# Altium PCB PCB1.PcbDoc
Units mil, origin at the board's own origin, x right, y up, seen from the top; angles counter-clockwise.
Board outline 6000 x 4000 mil, 2 copper layers (Top Layer, Bottom Layer); 39 components, 37 nets, 123 pads, 0 vias.
Unrouted connection lines stored in the file: 1.
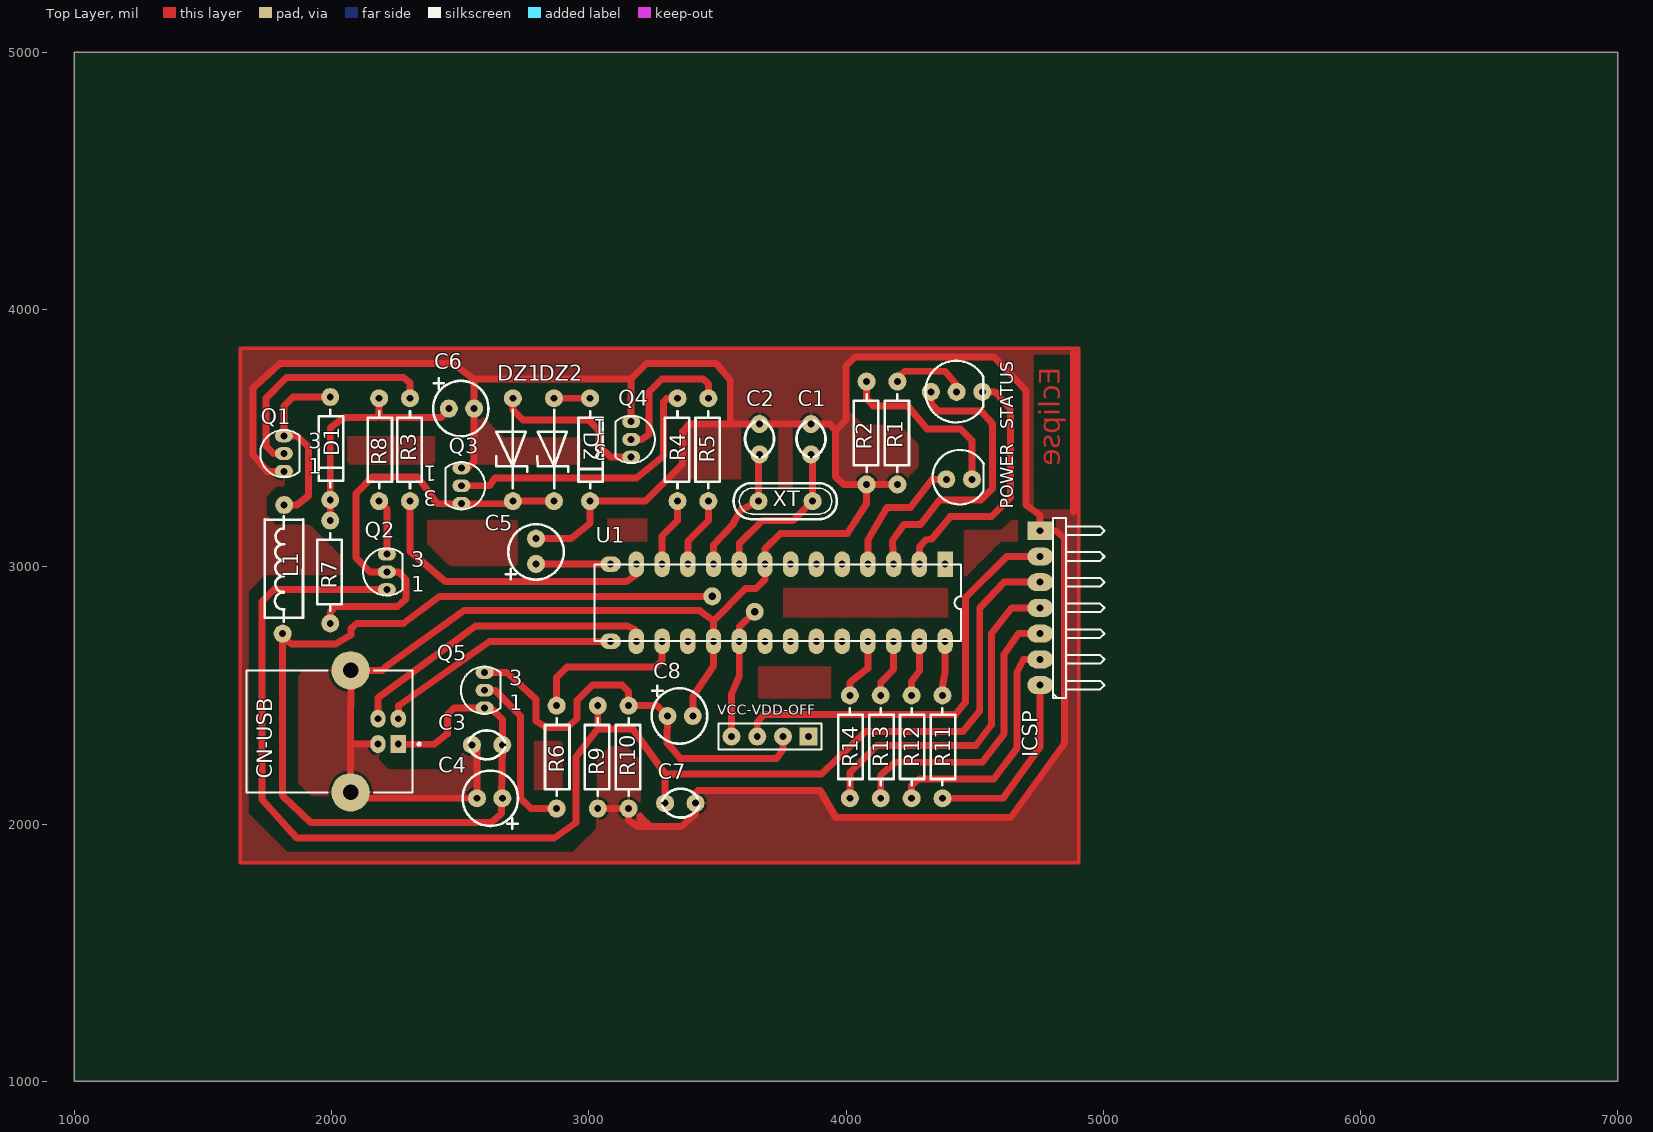
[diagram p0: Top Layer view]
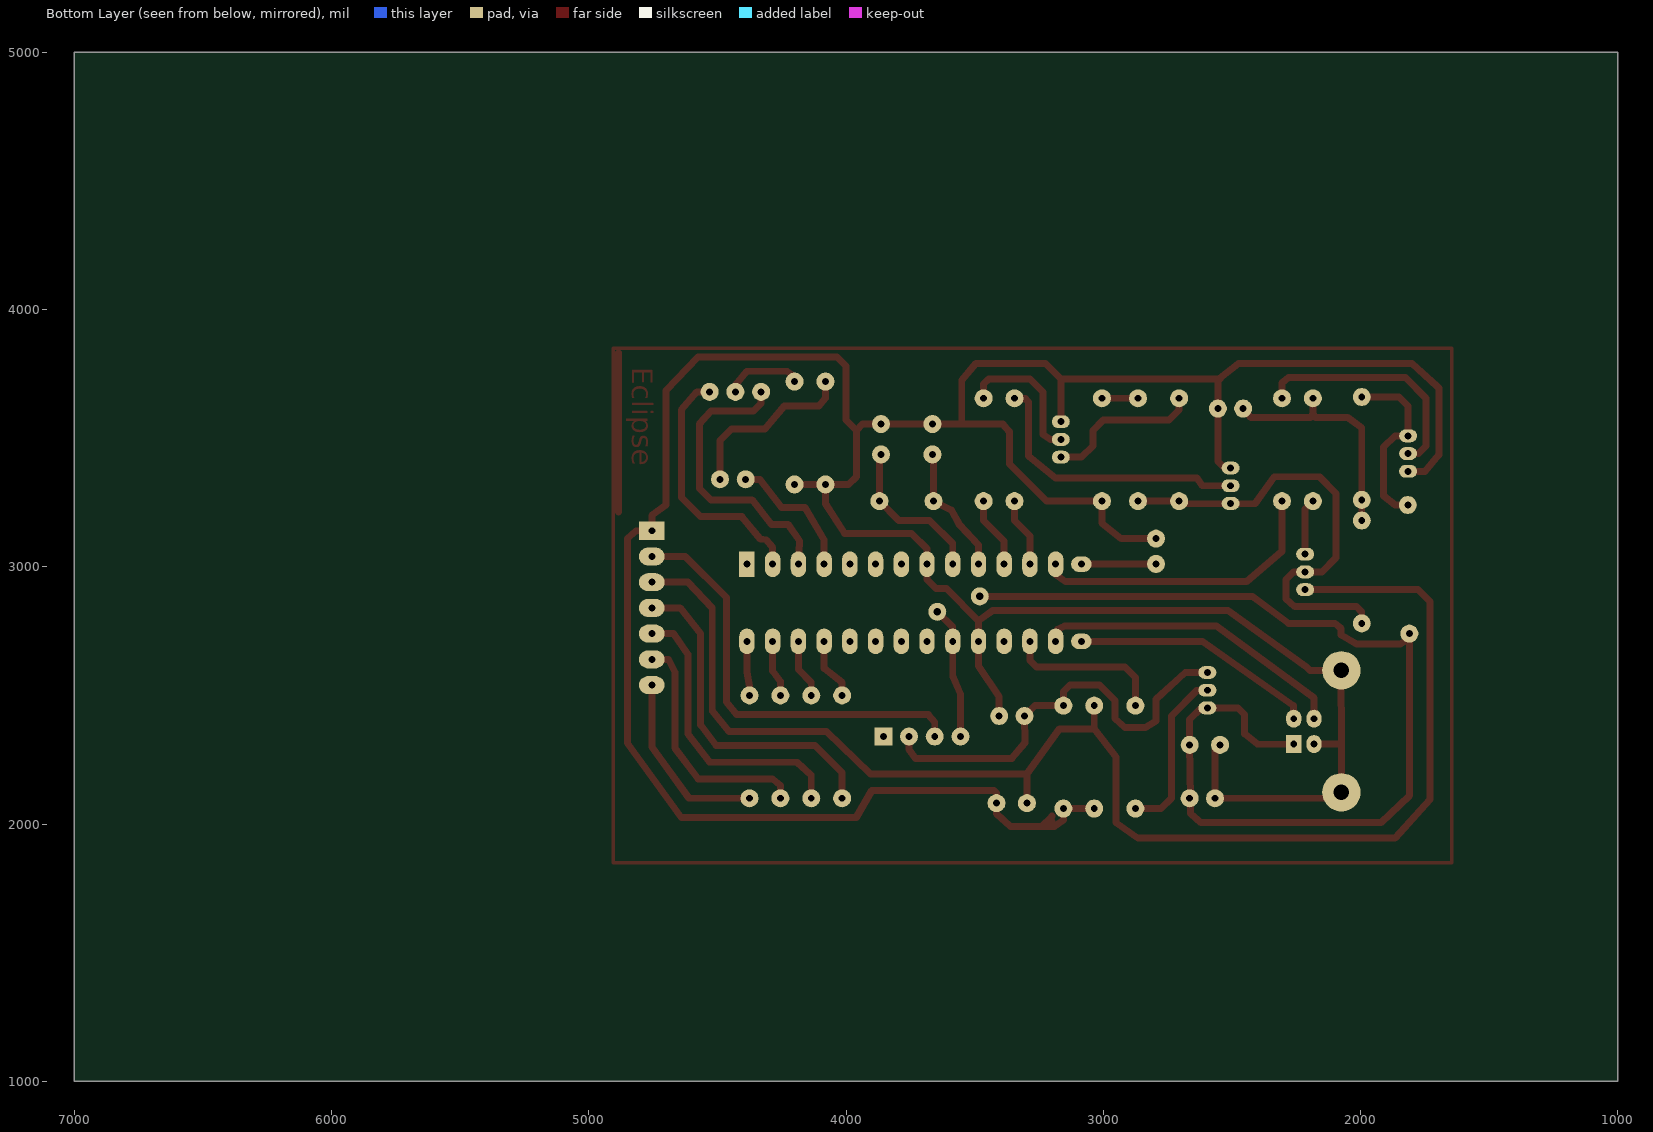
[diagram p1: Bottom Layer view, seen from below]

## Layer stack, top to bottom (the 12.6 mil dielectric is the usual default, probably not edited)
Top Layer: signal copper 1.4
Dielectric: dielectric 12.6, FR-4, Dk 4.8
Bottom Layer: signal copper 1.4

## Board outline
1000,1000 7000,1000 7000,5000 1000,5000

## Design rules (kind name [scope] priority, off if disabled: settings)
Clearance [All] p1: gap=10
ComponentClearance [All] p1: gap=10 collisioncheckmode=0
PolygonConnect [All] p1: connectstyle=Relief reliefconductorwidth=10 reliefentries=4 polygonreliefangle="90 Angle"
RoomDefinition "" [InComponentClass('Sheet1')] p1: confinementstyle=ConfineIn formatcopy=TRUE outline 1645,1850 4905,1850 4905,3850 1645,3850
RoutingLayers [All] p1: top layer=Horizontal bottom layer=Vertical
RoutingVias [All] p1: holewidth=28 width=50 viastyle="Through Hole" minholewidth=28 minwidth=50 maxholewidth=28 maxwidth=50
SolderMaskExpansion [All] p1: expansion=4
TestPointUsage [All] p1: valid=0 allowmultiple=FALSE
Testpoint [All] p1: side=15 testpointundercomponent=TRUE minsize=40 maxsize=100 preferedsize=60 minholesize=0 maxholesize=40 preferedholesize=32 testpointgrid=1 style=1023 order=-539222988
Width [All] p1: maxlimit=27 minlimit=27 preferedwidth=27
16 further rules are at their usual default settings.

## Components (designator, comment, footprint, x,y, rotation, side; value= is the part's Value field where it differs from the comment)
C1 "CC" "CC 0.15" 3865,3495 r270 top
C2 "CC" "CC 0.15" 3665,3495 r270 top
C3 "CC" "CC 0.15" 2605.57,2308.65 r0 top
C4 "Cap" CE-1.7 2615,2100 r180 top
C5 "Cap" CE-1.7 2795,3060 r90 top
C6 "Cap" CE-1.7 2505,3615 r0 top
C7 "CC" "CC 0.15" 3355,2080 r180 top
C8 "Cap" CE-1.7 3355,2420 r0 top
CN-USB "USB V2.0" USB2.5-2H4D 2220,2360 r180 top
D1 "Diodo" "DIODO 4MIL" 1995,3460 r270 top
D2 "Diodo" "DIODO 4MIL" 3005,3455 r270 top
DZ1 "5.6V" DIODOZ 2705,3455 r270 top
DZ2 "13V" DIODOZ 2865,3455 r270 top
ICSP "ICSP" HDR1X7H 4755,2540 r90 top (schematic designator JP1)
L1 "Inductor" L 1815,3040 r90 top
POWER "LED" LED-0 4440,3340 r0 top
Q1 "2N3904" "Q123 0.1" 1815,3440 r0 top
Q2 "2N3904" "Q123 0.1" 2215,2980 r0 top
Q3 "2N3904" "Q123 0.1" 2505,3315 r180 top
Q4 "2N3904" "Q123 0.1" 3165,3495 r180 top
Q5 "2N3906" "Q123 0.1" 2595,2520 r0 top
R1 "Res" "AXIAL 4MIL" 4200,3520 r90 top
R2 "Res" "AXIAL 4MIL" 4080,3520 r90 top
R3 "Res" "AXIAL 4MIL" 2305,3455 r90 top
R4 "Res" "AXIAL 4MIL" 3345,3455 r90 top
R5 "Res" "AXIAL 4MIL" 3465,3455 r90 top
R6 "Res" "AXIAL 4MIL" 2875,2260 r270 top
R7 "Res" "AXIAL 4MIL" 1995,2980 r90 top
R8 "Res" "AXIAL 4MIL" 2185,3455 r270 top
R9 "Res" "AXIAL 4MIL" 3035,2260 r90 top
R10 "Res" "AXIAL 4MIL" 3155,2260 r90 top
R11 "Res" "AXIAL 4MIL" 4375,2300 r270 top
R12 "Res" "AXIAL 4MIL" 4255,2300 r270 top
R13 "Res" "AXIAL 4MIL" 4135,2300 r270 top
R14 "Res" "AXIAL 4MIL" 4015,2300 r270 top
STATUS "LED" LED-BI 4380,3680 r0 top
U1 "PIC18F2550" DIP-28 3735,2860 r180 top
VCC-VDD-OFF "INPUT" HDR1X4 3855,2340 r180 top (schematic designator "CTRL 1")
XT "20MHz" "XT 0.17" 3765,3255 r0 top

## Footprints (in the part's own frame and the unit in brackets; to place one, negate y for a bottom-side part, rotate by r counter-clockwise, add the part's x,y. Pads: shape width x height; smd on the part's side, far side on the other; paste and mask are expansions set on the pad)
"AXIAL 4MIL" [mil]
  round 70 hole 27: 1(-200,0) 2(200,0)
  silkscreen extent -150,-45 150,50
"CC 0.15" [mil]
  round 70 hole 27: 1(-59.78,-1) 2(58.33,-1)
  silkscreen extent -74,-57 69,55
CE-1.7 [mil]
  round 70 hole 27: 1(-49,0) 2(49.43,0)
  silkscreen extent -110,-108 105,118
"DIODO 4MIL" [mil]
  round 70 hole 27: 1(-200,0) 2(200,0)
  silkscreen extent -150,-45 150,50
DIODOZ [mil]
  round 70 hole 27: 1(-200,0) 2(200,0)
  silkscreen extent -155,-65 150,56
DIP-28 [mil]
  rect 60x100 hole 27: 1(-650,-150)
  oval 60x100 hole 27: 2(-550,-150) 3(-450,-150) 4(-350,-150) 5(-250,-150) 6(-150,-150) 7(-50,-150) 8(50,-150) 9(150,-150) 10(250,-150) 11(350,-150) 12(450,-150) 13(550,-150) 16(550,150) 17(450,150) 18(350,150) 19(250,150) 20(150,150) 21(50,150) 22(-50,150) 23(-150,150) 24(-250,150) 25(-350,150) 26(-450,150) 27(-550,150) 28(-650,150)
  oval 80x60 hole 27: 14(650,-150) 15(650,150)
  silkscreen extent -713,-149 713,149
HDR1X4 [mil]
  rect 70x70 hole 27: 1(0,0)
  round 70 hole 27: 2(100,0) 3(200,0) 4(300,0)
  silkscreen extent -50,-50 350,50
HDR1X7H [mil]
  rect 70x100 hole 27: 1(600,0)
  oval 70x100 hole 27: 2(500,0) 3(400,0) 4(300,0) 5(200,0) 6(100,0) 7(0,0)
  silkscreen extent -50,-250 650,-50
L [mil]
  round 70 hole 27: 1(-300,5) 2(200,-1)
  silkscreen extent -253,-75 156,75
LED-0 [mil]
  round 70 hole 27: 1(-50,0) 2(50,0)
  silkscreen extent -103,-98 95,114
LED-BI [mil]
  round 70 hole 27: 1(-50,0) 2(150,0) 3(50,0)
  silkscreen extent -71,-119 153,121
"Q123 0.1" [mil]
  oval 70x50 hole 27: 1(0,-68.9) 2(0,0) 3(0,68.9)
  silkscreen extent -92,-92 61,92
USB2.5-2H4D [mil]
  rect 60x70 hole 27: 1(-39.37,49.21)
  oval 60x70 hole 27: 2(-39.37,-49.21) 3(39.37,-49.21) 4(39.37,49.21)
  round 149.61 hole 60: 5(146.06,237.01) 6(146.06,-237.01)
  silkscreen extent -125,-237 551,237
"XT 0.17" [mil]
  round 70 hole 27: 1(-105,0) 2(105,0)
  silkscreen extent -202,-70 200,70

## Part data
C1 C2 C3 C7: library part "Cap C", "Capacitor Ceramico"
C4 C5 C6 C8: library part "Cap E", "Capacitor Electrolitico"
CN-USB: library part "CON USB", "CON USB"
D1 D2: "Diodo de uso general"
DZ1 DZ2: library part "D Zener", "Diodo Zener"
ICSP: library part "Header 7", "Header, 7-Pin"
Q1 Q2 Q3 Q4: "NPN Uso general"
Q5: "PNP Uso General"
R1 R2 R3 R4 R5 R6 R7 R8 R9 R10 R11 R12 R13 R14: "Resistor"
STATUS: library part LED_BI, "LED_BI"
U1: "High Performance, Microcontroller with 10-Bit A/D, 16K EPROM, 28-Pin SOIC, Standard Volt Range, Extended Temperature"
VCC-VDD-OFF: library part "CON VDD/VCC", "CON VDD/VCC"
XT: library part XTAL, "Crystal Oscillator"

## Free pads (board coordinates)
  round 70 hole 30: 0(3480,2885) 1(3645,2825)

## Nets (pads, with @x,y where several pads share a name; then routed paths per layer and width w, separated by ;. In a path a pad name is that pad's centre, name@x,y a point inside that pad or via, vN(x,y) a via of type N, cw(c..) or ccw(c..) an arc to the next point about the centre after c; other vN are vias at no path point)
GND: C1.1 C2.1 C3.1 C4.2 C5.2 C6.2 C7.1 C8.2 CN-USB.4 CN-USB.5 CN-USB.6 D2.2 ICSP.1 Q1.1 Q3.1 Q4.1 R1.1 R2.1 R9.1 R10.1 U1.8 U1.19 | length 14553.9
  Top Layer w27: Q1.1 1750,3370 1695,3435 1695,3695 1703.01,3702.25 1800,3790 2475,3790 2546.57,3731.94 2548.97,3730 2554.43,3725.57 2554.43,3409.43 2528.9,3383.9 Q3.1 ; CN-USB.5@2070,2100 C4.2 2565.57,2287.86 C3.1 ; CN-USB.5 2074.37,2315 2075,2595.95 CN-USB.6 2197.01,2597.01 2210,2610 2515,2830 3430,2830 3485,2790 ; 2075,2315 2079.21,2310.79 CN-USB.4 ; 2545,3730 3165,3730 ; C5.2 2929.43,3109.43 3005,3170 D2.2 3220,3255 3365,3400 3365,3525 3390,3555 3550,3554.84 3664,3554.89 C1.1@3864,3554.98 ; R9.1 R10.1 ; R10.1@3160,2055 R10.1 ; Q4.1 3165,3730 ; 3200,2010 3220,1990 ; 3200,2032 3200,2030 3240,1990 ; C8.2 3405,2495 3485,2615 3485,2790 ; C7.1 C7.1@3419,2081 ; 3550,3555 3550,3725 3495,3790 3225,3790 3165,3730 ; C1.1 3935.22,3554.78 3960,3530 ; R2.1 4080,3245 4005,3130 3745,3130 3685,3070 3685,2950 3650,2915 3610,2915 3485,2790 ; R1.1 3990,3320 3960,3350 3960,3530 ; 4885,3213 4885,3832 ; R10.1 3155,2015 3187.16,1992.03 3190,1990 3360,1990 3414.78,2039.78 3414.78,2119.78 3425,2130 3900,2130 3960,2025 4640,2025 4850,2315 4850,3110 4815,3140 ICSP.1 4755,3200 4700,3240 4700,3685 4575,3815 4035,3815 4000,3780 4000,3570 3960,3530
NetC1_2: C1.2 U1.9 XT.2 | length 617.5
  Top Layer w27: U1.9 3585,3090 3675,3180 3795,3180 XT.2 3870,3430.67 C1.2
NetC2_2: C2.2 U1.10 XT.1 | length 508.9
  Top Layer w27: U1.10 3485,3085 3560,3165 3590,3220 XT.1 3660,3432.67 C2.2
NetC5_1: C5.1 U1.14 | length 290.4
  Top Layer w27: C5.1 3084,3011 U1.14
NetC6_1: C6.1 D1.2 R7.2 R8.1 | length 926.2
  Top Layer w27: R7.2 1995,3540 2050,3580 2175,3580 2185,3595 ; R8.1 2185,3595 ; C6.1 2426,3580 2195,3580 2185,3595
NetCN-USB_2: CN-USB.2 U1.15 | length 960
  Top Layer w27: CN-USB.2@2259.37,2404.21 2260,2460 2615,2710 U1.15
NetCN-USB_3: CN-USB.3 U1.16 | length 1221.6
  Top Layer w27: CN-USB.3 2180,2490 2560,2770 3150,2770 3180,2755 U1.16
NetD1_1: D1.1 L1.2 Q1.3 | length 719.8
  Top Layer w27: L1.2 1865,3240 1910,3275 1910,3465 1866.1,3508.9 Q1.3 1815,3625 1850,3660 D1.1
NetD2_1: D2.1 DZ2.1 | length 140
  Top Layer w27: DZ2.1 D2.1
NetDZ1_1: DZ1.1 Q4.3 | length 616.3
  Top Layer w27: DZ1.1 2705,3610 2745,3570 3000,3570 3040,3530 3040,3470 3083.9,3426.1 Q4.3
NetDZ1_2: DZ1.2 DZ2.2 Q2.2 Q3.3 R7.1 | length 1767.2
  Top Layer w27: R7.1 1995,2825 2015,2845 2255,2845 2290,2875 2290,2950 2260,2980 2150,2980 2095,3035 2095,3285 2160,3350 2335,3350 2410,3245 Q3.3 2675,3245 DZ1.2 DZ2.2
NetJP1_4: ICSP.4 R14.2 | length 1331.6
  Top Layer w27: R14.2@4015,2095 4015,2200 4120,2305 4505,2305 4565,2385 4565,2740 4645,2840 ICSP.4
NetJP1_5: ICSP.5 R13.2 | length 1135.4
  Top Layer w27: R13.2 4135,2190 4190,2240 4530,2240 4615,2350 4615,2660 4670,2740 ICSP.5
NetJP1_6: ICSP.6 R12.2 | length 945
  Top Layer w27: R12.2 4255,2150 4285,2175 4575,2175 4665,2295 4665,2590 4690,2640 ICSP.6
NetJP1_7: ICSP.7 R11.2 | length 722
  Top Layer w27: R11.2 4610,2100 4755,2300 ICSP.7
NetPOWER_1: POWER.1 U1.4 | length 524.8
  Top Layer w27: U1.4 4085,3105 4160,3230 4250,3230 4335,3340 POWER.1
NetPOWER_2: POWER.2 R2.2 | length 699.8
  Top Layer w27: R2.2 4080,3655 4105,3625 4240,3625 4315,3535 4445,3535 4490,3490 POWER.2
NetQ1_2: Q1.2 R3.2 | length 927.6
  Top Layer w27: Q1.2 1775,3440 1745,3470 1745,3655 1825,3735 2280,3735 2305,3715 R3.2
NetQ2_3: Q2.3 R8.2 | length 218.5
  Top Layer w27: R8.2 2215,3225 Q2.3
NetQ3_2: Q3.2 R4.2 | length 1102.4
  Top Layer w27: Q3.2 2615,3315 2635,3345 3185,3345 3290,3430 3290,3640 3305,3655 R4.2
NetQ4_2: Q4.2 R5.2 | length 555.1
  Top Layer w27: Q4.2 3205,3495 3235,3515 3235,3680 3285,3730 3445,3730 3465,3710 R5.2
NetQ5_2: Q5.2 R6.2 | length 658
  Top Layer w27: Q5.2 2635,2520 2735,2420 2735,2100 2775,2060 R6.2
NetR1_2: R1.2 STATUS.3 | length 307.1
  Top Layer w27: R1.2 4200,3740 4230,3760 4385,3760 4430,3705 STATUS.3
NetR3_1: R3.1 U1.13 | length 1167.8
  Top Layer w27: R3.1 2305,3060 2443,2942 3147,2942 3185,2970 U1.13
NetR4_1: R4.1 U1.12 | length 269.9
  Top Layer w27: U1.12 3285,3120 3345,3180 R4.1
NetR5_1: R5.1 U1.11 | length 278.1
  Top Layer w27: U1.11 3385,3100 3465,3180 R5.1
NetR6_1: R6.1 U1.17 | length 621.9
  Top Layer w27: R6.1 2875,2570 2915,2610 3260,2610 3285,2635 U1.17
NetR11_1: R11.1 U1.28 | length 210.9
  Top Layer w27: R11.1 4375,2535 4385,2590 U1.28
NetR12_1: R12.1 U1.27 | length 220
  Top Layer w27: R12.1 4255,2555 4285,2595 U1.27
NetR13_1: R13.1 U1.26 | length 230.7
  Top Layer w27: R13.1 4135,2550 4185,2600 U1.26
NetR14_1: R14.1 U1.25 | length 244
  Top Layer w27: R14.1 4015,2550 4085,2605 U1.25
NetSTATUS_1: STATUS.1 U1.3 | length 1148.6
  Top Layer w27: U1.3 4180,3100 4225,3165 4290,3165 4365,3260 4525,3260 4570,3305 4570,3555 4525,3605 4360,3605 4330,3635 STATUS.1
NetSTATUS_2: STATUS.2 U1.2 | length 988.4
  Top Layer w27: U1.2 4285,3075 4310,3105 4333,3108 4405,3195 4565,3195 4640,3270 4640,3610 4580,3680 STATUS.2
VCC: C3.2 C4.1 CN-USB.1 L1.1 pad.0 pad.1 Q5.1 U1.20 VCC-VDD-OFF.4 | length 4692.2
  Top Layer w27: L1.1@1810,2720 1845,2700 2015,2700 2075,2735 2075,2760 2100,2780 2280,2780 2420,2885 pad.0 ; L1.1 1810,2110 1920,2005 2620,2005 2660,2040 2660.9,2100.05 2664,2307.55 C3.2 2663.9,2406.1 2618.9,2451.1 2476.1,2451.1 2450,2425 2450,2350 2400,2310 CN-USB.1 ; VCC-VDD-OFF.4 3555,2505 3585,2575 3585,2765 pad.1
VCC-VDD: ICSP.2 VCC-VDD-OFF.3 | length 1664.4
  Top Layer w27: VCC-VDD-OFF.3 3655,2395 3680,2425 4425,2425 4465,2475 4465,2880 4625,3040 ICSP.2
VDD: C8.1 Q5.3 R10.2 VCC-VDD-OFF.2 | length 1684.5
  Top Layer w27: Q5.3 2681.1,2588.9 2795,2485 2795,2400 2835,2375 2915,2375 2955,2410 2955,2480 3015,2540 3130,2540 3155,2515 R10.2 3266,2460 C8.1 3305,2315 3355,2255 3730,2255 3755,2290 VCC-VDD-OFF.2
VPP-RST: C7.2 ICSP.3 Q2.1 R9.2 | length 5535.2
  Top Layer w27: Q2.1 1776.1,2911.1 1730,2865 1730,2095 1865,1945 2865,1945 2950,2005 2950,2260 3035,2370 ; R9.2 3035,2370 ; C7.2 3296.67,2195 ; ICSP.3 4615,2940 4520,2840 4520,2440 4455,2360 4075,2360 3905,2195 3296.67,2195 ; 3035,2370 3170,2370 3296.67,2195
pads on no net: U1.1 U1.5 U1.6 U1.7 U1.18 U1.21 U1.22 U1.23 U1.24 VCC-VDD-OFF.1
copper on no net: | length 10515
  Top Layer w14: 1645,3850 1645,1850 4905,1850 4905,3850 1650,3850

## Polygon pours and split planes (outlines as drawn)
GND on Top Layer (hatched 90Degree grid 8 track 8): 3307.99,3342.99 3590,3342.99 3590,3554.78 3390,3554.78 3365,3529.78 3365,3400 3310,3345
GND on Top Layer (hatched 90Degree grid 8 track 8): 3740,3540 3740,3305 3790,3305 3790,3540
GND on Top Layer (hatched 90Degree grid 8 track 8): 4010,3605 4065,3550 4205,3550 4280,3475 4280,3390 4210,3320 3990,3320 3960,3350 3960,3560 4005,3605
GND on Top Layer (hatched 90Degree grid 8 track 8): 3660,2610 3940,2610 3940,2490 3660,2490
GND on Top Layer (hatched 90Degree grid 8 track 8): 3760,2920 3760,2805 4395,2805 4395,2915 3760,2915
GND on Top Layer (hatched 90Degree grid 8 track 8): 4460,3140 4605,3140 4645,3180 4665,3180 4665,3100 4600,3100 4470,2970 4460,2960
GND on Top Layer (hatched 90Degree grid 8 track 8): 3035,2060 3035,2250 3085,2300 3145,2300 3200,2245 3200,1984 3032,1984 3032,2060
GND on Top Layer (hatched 90Degree grid 8 track 8): 2375,3180 2720,3180 2720,3005 2460,3005 2385,3080 2375,3090
GND on Top Layer (hatched 90Degree grid 8 track 8): 2554.43,3615 2669.43,3500 2965,3500 2965,3400 2555,3400 2555,3615
GND on Top Layer (hatched 90Degree grid 8 track 8): 2065,3505 2400,3505 2400,3400 2065,3400
GND on Top Layer (hatched 90Degree grid 8 track 8): 2073.94,2597.01 1895,2597.01 1872.99,2575 1872.99,2160 1922.99,2110 2073.94,2110
GND on Top Layer (hatched 90Degree grid 8 track 8): 2180.63,2310.79 2180.63,2250 2220,2210.63 2505,2210.63 2505,2270 2542.65,2307.65 2565.57,2284.72 2565.57,2100 2070,2100 2070,2305 2180.63,2305
GND on Top Layer (hatched 90Degree grid 8 track 8): 2790,2320 2895,2320 2895,2135 2790,2135
GND on Top Layer (hatched 90Degree grid 8 track 8): 3075,3185 3225,3185 3225,3100 3075,3100
GND on Top Layer (hatched 90Degree grid 8 track 8): 1645,3850 4905,3850 4905,1850 1645,1850 1645,3835 1745,3735 1705,3695 1705,3435 1770,3370 1815,3370 1815,3315 1785,3315 1745,3275 1745,3200 1785,3160 1915,3160 2000,3075 2040,3035 2040,2970 1740,2970 1675,2905 1675,2040 1825,1890 2940,1890 3034,1984 3365,1984 3414.78,2033.78 3414.78,2119.78 3425,2130 3900,2130 3920,2110 3920,2080 3955,2045 3955,2025 4640,2025 4665,2050 4665,2075 4735,2145 4735,2165 4795,2225 4795,2250 4850,2305 4850,3110 4820,3140 4755,3140 4755,3200 4705,3250 4705,3685 4575,3815 4035,3815 4000,3780 4000,3576 3961.78,3537.78 3944.78,3554.78 3552,3554.78 3552,3725 3487,3790 3218.25,3790 3165,3736.75 2554.43,3736.75 2547.68,3730 2487.68,3790 1810,3790 1755,3735 1740,3735 1645,3830 1640,3830

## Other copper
Top Layer:
  text "Eclipse" at 4830,3775 h80 r90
